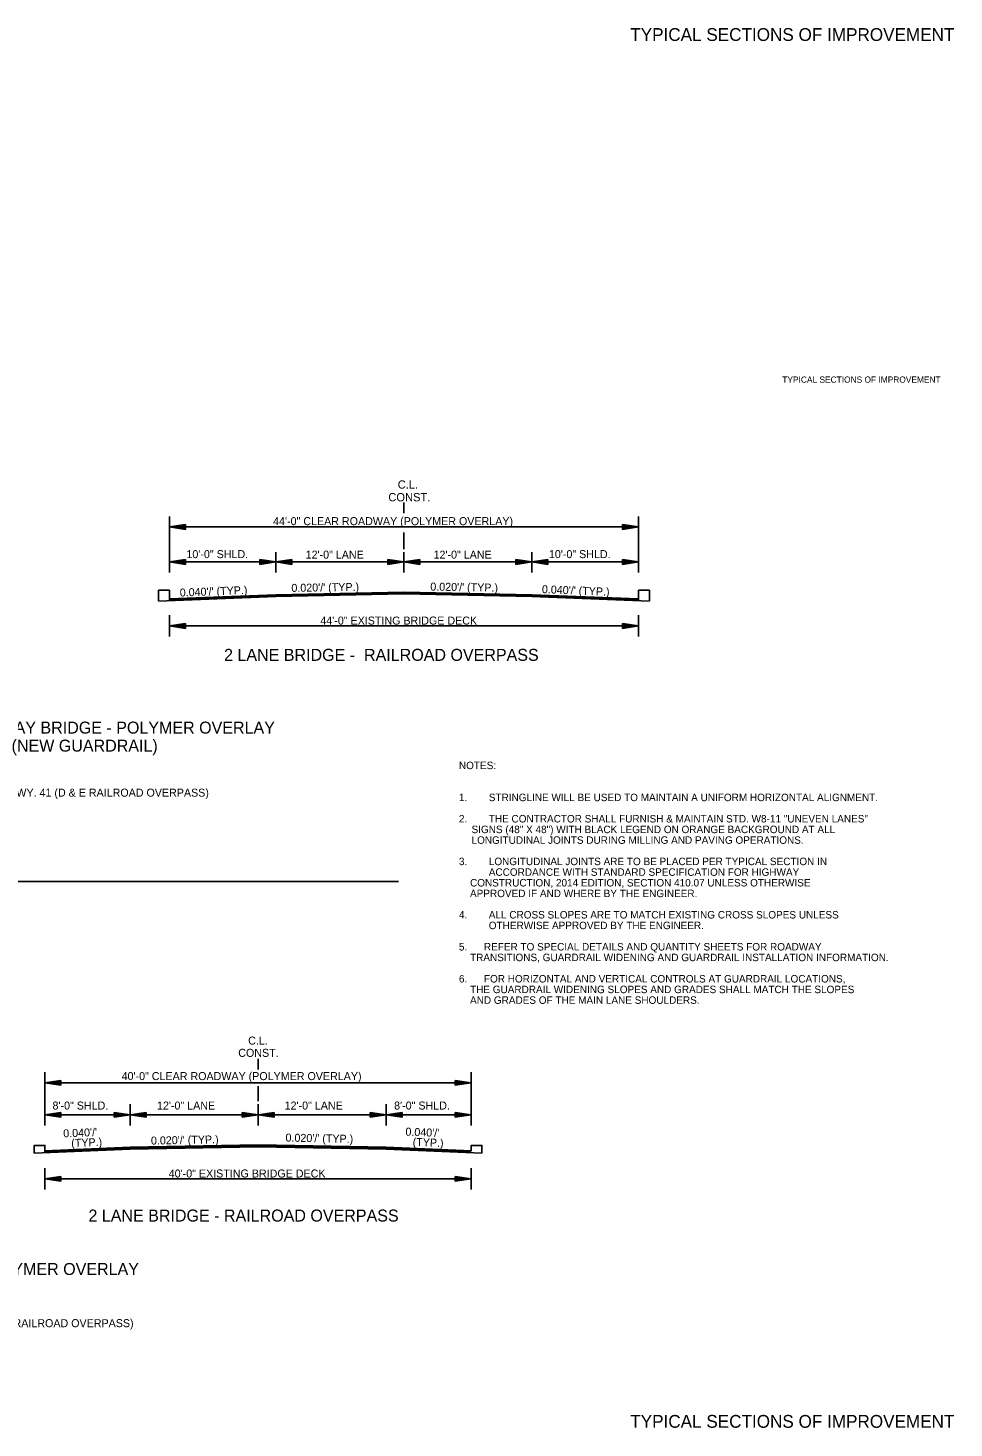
# Model space of a CAD drawing. Extents: x 545241 to 1930787, y -1971772 to 596640.
# Drawn here: x 547399 to 548268, y -1956172 to -1954859 of the extents above; entities that cross this region are included whole.
import ezdxf

# ---------------------------------------------------------------- set-up
doc = ezdxf.new("R2010")
doc.units = 0
for name, color, linetype in [('R_Border', 7, 'Continuous'), ('R_Border Notes', 7, 'Continuous'), ('R_Border Prem', 7, 'Continuous'), ('R_Draft', 7, 'Continuous')]:
    doc.layers.add(name, color=color, linetype=linetype)

# ---------------------------------------------------------------- blocks, each defined once
blk = doc.blocks.new('ARROW')
at = {"layer": 'R_Draft'}
for p, q in [((-2, 0.3), (0, 0)), ((-2, 0.3), (-2, -0.3)), ((-2, 0.25), (-0.334, 0)), ((-2, 0.199), (-0.678, 0)), ((-2, 0.149), (-1.011, 0)), ((-2, 0.097), (-1.35, 0)), ((-2, 0.047), (-1.684, 0)), ((-2, -0.3), (0, 0)), ((-2, -0.098), (-1.35, 0)), ((-2, -0.199), (-0.678, 0)), ((-2, -0.25), (-0.334, 0)), ((-2, -0.149), (-1.011, 0)), ((-2, -0.047), (-1.684, 0))]:
    blk.add_line(p, q, dxfattribs=at)

msp = doc.modelspace()

# ---------------------------------------------------------------- linework, layer by layer
at = {"layer": 'R_Border'}
for p, q in [((547521.7, -1955386.5), (547521.7, -1955396.4)), ((547531.9, -1955386.5), (547521.7, -1955386.5)), ((547531.9, -1955396), (547531.9, -1955386.5)), ((547971.9, -1955396), (547971.9, -1955386.5)), ((547971.9, -1955386.5), (547982.1, -1955386.5)), ((547982.1, -1955386.5), (547982.1, -1955396.4)), ((546718.9, -1955659.5), (547746.9, -1955659.5)), ((547615.1, -1955825.8), (547615.1, -1955835.8)), ((547415.1, -1955838.3), (547415.1, -1955888.3)), ((547815.1, -1955838.3), (547815.1, -1955888.3)), ((547415.1, -1955848.3), (547815.1, -1955848.3)), ((547615.1, -1955851.3), (547615.1, -1955865.3)), ((547495.1, -1955868.3), (547495.1, -1955888.3)), ((547615.1, -1955868.3), (547615.1, -1955888.3)), ((547735.1, -1955868.3), (547735.1, -1955888.3)), ((547415.1, -1955878.3), (547815.1, -1955878.3)), ((547415.1, -1955928.3), (547415.1, -1955948.3)), ((547815.1, -1955928.3), (547815.1, -1955948.3)), ((547415.1, -1955938.3), (547815.1, -1955938.3))]:
    msp.add_line(p, q, dxfattribs=at)
for points in [[(547415.1, -1955913.4), (547415.1, -1955906.9), (547405.1, -1955906.9), (547405.1, -1955914.1)], [(547405.1, -1955914.1), (547495.1, -1955910.5), (547615.1, -1955908.1), (547735.1, -1955910.5), (547825.1, -1955914.1)], [(547415.1, -1955911.9), (547495.1, -1955908.7), (547615.1, -1955906.3), (547735.1, -1955908.7), (547815.1, -1955911.9)], [(547415.1, -1955912.2), (547495.1, -1955909), (547615.1, -1955906.6), (547735.1, -1955909), (547815.1, -1955912.2)], [(547415.1, -1955912.5), (547495.1, -1955909.3), (547615.1, -1955906.9), (547735.1, -1955909.3), (547815.1, -1955912.5)], [(547415.1, -1955912.8), (547495.1, -1955909.6), (547615.1, -1955907.2), (547735.1, -1955909.6), (547815.1, -1955912.8)], [(547415.1, -1955913.1), (547495.1, -1955909.9), (547615.1, -1955907.5), (547735.1, -1955909.9), (547815.1, -1955913.1)], [(547415.1, -1955913.4), (547495.1, -1955910.2), (547615.1, -1955907.8), (547735.1, -1955910.2), (547815.1, -1955913.4)], [(547815.1, -1955911.9), (547815.1, -1955906.9), (547825.1, -1955906.9), (547825.1, -1955914.1)]]:
    msp.add_lwpolyline(points, dxfattribs=at)
at = {"layer": 'R_Draft'}
for p, q in [((547751.9, -1955314.2), (547751.9, -1955304.2)), ((547531.9, -1955370), (547531.9, -1955317.3)), ((547971.9, -1955370), (547971.9, -1955317.3)), ((547546.9, -1955325), (547531.9, -1955327.2)), ((547971.9, -1955327.2), (547531.9, -1955327.2)), ((547546.9, -1955329.5), (547531.9, -1955327.2)), ((547546.9, -1955325.3), (547534.4, -1955327.2)), ((547546.9, -1955329.1), (547534.4, -1955327.2)), ((547546.9, -1955325.7), (547537, -1955327.2)), ((547546.9, -1955328.7), (547537, -1955327.2)), ((547546.9, -1955326.1), (547539.5, -1955327.2)), ((547546.9, -1955328.3), (547539.5, -1955327.2)), ((547546.9, -1955326.5), (547542, -1955327.2)), ((547546.9, -1955327.9), (547542, -1955327.2)), ((547546.9, -1955326.9), (547544.5, -1955327.2)), ((547546.9, -1955327.6), (547544.5, -1955327.2)), ((547546.9, -1955325), (547546.9, -1955329.5)), ((547921.9, -1955327.2), (547641.9, -1955327.2)), ((547956.9, -1955325), (547971.9, -1955327.2)), ((547956.9, -1955329.5), (547956.9, -1955325)), ((547956.9, -1955325.3), (547969.4, -1955327.2)), ((547956.9, -1955325.7), (547966.8, -1955327.2)), ((547956.9, -1955326.1), (547964.3, -1955327.2)), ((547956.9, -1955326.5), (547961.8, -1955327.2)), ((547956.9, -1955326.9), (547959.3, -1955327.2)), ((547956.9, -1955329.5), (547971.9, -1955327.2)), ((547956.9, -1955327.9), (547961.8, -1955327.2)), ((547956.9, -1955328.7), (547966.8, -1955327.2)), ((547956.9, -1955329.1), (547969.4, -1955327.2)), ((547956.9, -1955328.3), (547964.3, -1955327.2)), ((547956.9, -1955327.6), (547959.3, -1955327.2)), ((547751.9, -1955348), (547751.9, -1955332.3)), ((547631.9, -1955370), (547631.9, -1955350.9)), ((547751.9, -1955370), (547751.9, -1955350.9)), ((547871.9, -1955370), (547871.9, -1955350.9)), ((547546.9, -1955357.8), (547531.9, -1955360)), ((547631.9, -1955360), (547531.9, -1955360)), ((547546.9, -1955362.3), (547531.9, -1955360)), ((547546.9, -1955358.2), (547534.4, -1955360)), ((547546.9, -1955361.9), (547534.4, -1955360)), ((547546.9, -1955358.5), (547537, -1955360)), ((547546.9, -1955361.5), (547537, -1955360)), ((547546.9, -1955358.9), (547539.5, -1955360)), ((547546.9, -1955361.2), (547539.5, -1955360)), ((547546.9, -1955359.3), (547542, -1955360)), ((547546.9, -1955360.8), (547542, -1955360)), ((547546.9, -1955359.7), (547544.5, -1955360)), ((547546.9, -1955360.4), (547544.5, -1955360)), ((547546.9, -1955357.8), (547546.9, -1955362.3)), ((547616.9, -1955357.8), (547631.9, -1955360)), ((547616.9, -1955357.8), (547616.9, -1955362.3)), ((547616.9, -1955358.2), (547629.4, -1955360)), ((547616.9, -1955358.5), (547626.8, -1955360)), ((547616.9, -1955358.9), (547624.3, -1955360)), ((547616.9, -1955359.3), (547621.8, -1955360)), ((547616.9, -1955359.7), (547619.3, -1955360)), ((547616.9, -1955362.3), (547631.9, -1955360)), ((547616.9, -1955360.8), (547621.8, -1955360)), ((547616.9, -1955361.5), (547626.8, -1955360)), ((547616.9, -1955361.9), (547629.4, -1955360)), ((547616.9, -1955361.2), (547624.3, -1955360)), ((547616.9, -1955360.4), (547619.3, -1955360)), ((547646.9, -1955357.8), (547631.9, -1955360)), ((547751.9, -1955360), (547631.9, -1955360)), ((547646.9, -1955362.3), (547631.9, -1955360)), ((547646.9, -1955358.2), (547634.4, -1955360)), ((547646.9, -1955361.9), (547634.4, -1955360)), ((547646.9, -1955358.5), (547637, -1955360)), ((547646.9, -1955361.5), (547637, -1955360)), ((547646.9, -1955358.9), (547639.5, -1955360)), ((547646.9, -1955361.2), (547639.5, -1955360)), ((547646.9, -1955359.3), (547642, -1955360)), ((547646.9, -1955360.8), (547642, -1955360)), ((547646.9, -1955359.7), (547644.5, -1955360)), ((547646.9, -1955360.4), (547644.5, -1955360)), ((547646.9, -1955357.8), (547646.9, -1955362.3)), ((547736.9, -1955357.8), (547751.9, -1955360)), ((547736.9, -1955357.8), (547736.9, -1955362.3)), ((547736.9, -1955358.2), (547749.4, -1955360)), ((547736.9, -1955358.5), (547746.8, -1955360)), ((547736.9, -1955358.9), (547744.3, -1955360)), ((547736.9, -1955359.3), (547741.8, -1955360)), ((547736.9, -1955359.7), (547739.3, -1955360)), ((547736.9, -1955362.3), (547751.9, -1955360)), ((547736.9, -1955360.8), (547741.8, -1955360)), ((547736.9, -1955361.5), (547746.8, -1955360)), ((547736.9, -1955361.9), (547749.4, -1955360)), ((547736.9, -1955361.2), (547744.3, -1955360)), ((547736.9, -1955360.4), (547739.3, -1955360)), ((547766.9, -1955357.8), (547751.9, -1955360)), ((547871.9, -1955360), (547751.9, -1955360)), ((547766.9, -1955362.3), (547751.9, -1955360)), ((547766.9, -1955358.2), (547754.4, -1955360)), ((547766.9, -1955361.9), (547754.4, -1955360)), ((547766.9, -1955358.5), (547757, -1955360)), ((547766.9, -1955361.5), (547757, -1955360)), ((547766.9, -1955358.9), (547759.5, -1955360)), ((547766.9, -1955361.2), (547759.5, -1955360)), ((547766.9, -1955359.3), (547762, -1955360)), ((547766.9, -1955360.8), (547762, -1955360)), ((547766.9, -1955359.7), (547764.5, -1955360)), ((547766.9, -1955360.4), (547764.5, -1955360)), ((547766.9, -1955357.8), (547766.9, -1955362.3)), ((547856.9, -1955357.8), (547871.9, -1955360)), ((547856.9, -1955357.8), (547856.9, -1955362.3)), ((547856.9, -1955358.2), (547869.4, -1955360)), ((547856.9, -1955358.5), (547866.8, -1955360)), ((547856.9, -1955358.9), (547864.3, -1955360)), ((547856.9, -1955359.3), (547861.8, -1955360)), ((547856.9, -1955359.7), (547859.3, -1955360)), ((547856.9, -1955362.3), (547871.9, -1955360)), ((547856.9, -1955360.8), (547861.8, -1955360)), ((547856.9, -1955361.5), (547866.8, -1955360)), ((547856.9, -1955361.9), (547869.4, -1955360)), ((547856.9, -1955361.2), (547864.3, -1955360)), ((547856.9, -1955360.4), (547859.3, -1955360)), ((547886.9, -1955357.8), (547871.9, -1955360)), ((547871.9, -1955360), (547971.9, -1955360)), ((547886.9, -1955362.3), (547871.9, -1955360)), ((547886.9, -1955358.2), (547874.4, -1955360)), ((547886.9, -1955361.9), (547874.4, -1955360)), ((547886.9, -1955358.5), (547877, -1955360)), ((547886.9, -1955361.5), (547877, -1955360)), ((547886.9, -1955358.9), (547879.5, -1955360)), ((547886.9, -1955361.2), (547879.5, -1955360)), ((547886.9, -1955359.3), (547882, -1955360)), ((547886.9, -1955360.8), (547882, -1955360)), ((547886.9, -1955359.7), (547884.5, -1955360)), ((547886.9, -1955360.4), (547884.5, -1955360)), ((547886.9, -1955357.8), (547886.9, -1955362.3)), ((547956.9, -1955357.8), (547971.9, -1955360)), ((547956.9, -1955357.8), (547956.9, -1955362.3)), ((547956.9, -1955358.2), (547969.4, -1955360)), ((547956.9, -1955358.5), (547966.8, -1955360)), ((547956.9, -1955358.9), (547964.3, -1955360)), ((547956.9, -1955359.3), (547961.8, -1955360)), ((547956.9, -1955359.7), (547959.3, -1955360)), ((547956.9, -1955362.3), (547971.9, -1955360)), ((547956.9, -1955360.8), (547961.8, -1955360)), ((547956.9, -1955361.5), (547966.8, -1955360)), ((547956.9, -1955361.9), (547969.4, -1955360)), ((547956.9, -1955361.2), (547964.3, -1955360)), ((547956.9, -1955360.4), (547959.3, -1955360)), ((547631.9, -1955392.3), (547521.7, -1955396.7)), ((547631.9, -1955390.7), (547531.9, -1955394.7)), ((547631.9, -1955391), (547531.9, -1955395)), ((547631.9, -1955391.3), (547531.9, -1955395.3)), ((547631.9, -1955391.6), (547531.9, -1955395.6)), ((547631.9, -1955392), (547531.9, -1955396)), ((547751.9, -1955388.3), (547631.9, -1955390.7)), ((547751.9, -1955388.6), (547631.9, -1955391)), ((547751.9, -1955388.9), (547631.9, -1955391.3)), ((547751.9, -1955389.2), (547631.9, -1955391.6)), ((547751.9, -1955389.5), (547631.9, -1955392)), ((547751.9, -1955389.8), (547631.9, -1955392.3)), ((547751.9, -1955390), (547631.9, -1955392.4)), ((547751.9, -1955388.3), (547871.9, -1955390.7)), ((547751.9, -1955388.6), (547871.9, -1955391)), ((547751.9, -1955388.9), (547871.9, -1955391.3)), ((547751.9, -1955389.2), (547871.9, -1955391.6)), ((547751.9, -1955389.5), (547871.9, -1955392)), ((547751.9, -1955389.8), (547871.9, -1955392.3)), ((547751.9, -1955390), (547871.9, -1955392.4)), ((547871.9, -1955390.7), (547971.9, -1955394.7)), ((547871.9, -1955391), (547971.9, -1955395)), ((547871.9, -1955391.3), (547971.9, -1955395.3)), ((547871.9, -1955391.6), (547971.9, -1955395.6)), ((547871.9, -1955392), (547971.9, -1955396)), ((547871.9, -1955392.3), (547982.1, -1955396.7)), ((547531.9, -1955410), (547531.9, -1955430)), ((547971.9, -1955409.8), (547971.9, -1955429.8)), ((547546.9, -1955417.8), (547531.9, -1955420)), ((547546.9, -1955422.3), (547531.9, -1955420)), ((547971.9, -1955420), (547531.9, -1955420)), ((547546.9, -1955418.1), (547534.4, -1955420)), ((547546.9, -1955421.9), (547534.4, -1955420)), ((547546.9, -1955418.5), (547537, -1955420)), ((547546.9, -1955421.5), (547537, -1955420)), ((547546.9, -1955418.9), (547539.5, -1955420)), ((547546.9, -1955421.1), (547539.5, -1955420)), ((547546.9, -1955419.3), (547542, -1955420)), ((547546.9, -1955420.7), (547542, -1955420)), ((547546.9, -1955419.7), (547544.5, -1955420)), ((547546.9, -1955420.4), (547544.5, -1955420)), ((547546.9, -1955417.8), (547546.9, -1955422.3)), ((547956.9, -1955417.8), (547971.9, -1955420)), ((547956.9, -1955422.3), (547956.9, -1955417.8)), ((547956.9, -1955418.1), (547969.4, -1955420)), ((547956.9, -1955418.5), (547966.8, -1955420)), ((547956.9, -1955418.9), (547964.3, -1955420)), ((547956.9, -1955419.3), (547961.8, -1955420)), ((547956.9, -1955419.7), (547959.3, -1955420)), ((547956.9, -1955422.3), (547971.9, -1955420)), ((547956.9, -1955420.7), (547961.8, -1955420)), ((547956.9, -1955421.5), (547966.8, -1955420)), ((547956.9, -1955421.9), (547969.4, -1955420)), ((547956.9, -1955421.1), (547964.3, -1955420)), ((547956.9, -1955420.4), (547959.3, -1955420))]:
    msp.add_line(p, q, dxfattribs=at)

# ---------------------------------------------------------------- block references
at = {"layer": 'R_Border', "xscale": 7.5, "yscale": 7.5, "rotation": 180}
for p in [(547415.1, -1955848.3), (547415.1, -1955878.3), (547495.1, -1955878.3), (547615.1, -1955878.3), (547735.1, -1955878.3), (547415.1, -1955938.3)]:
    msp.add_blockref('ARROW', p, dxfattribs=at)
at = {"layer": 'R_Border', "xscale": 7.5, "yscale": 7.5}
for p in [(547815.1, -1955848.3), (547495.1, -1955878.3), (547615.1, -1955878.3), (547735.1, -1955878.3), (547815.1, -1955878.3), (547815.1, -1955938.3)]:
    msp.add_blockref('ARROW', p, dxfattribs=at)

# ---------------------------------------------------------------- texts
at = {"layer": 'R_Border'}
for s, height, rotation, p in [('TYPICAL SECTIONS OF IMPROVEMENT', 12, 360, (547964.2, -1954871.6)), ("0.040'/'", 7.5, 2.2916, (547432.5, -1955899.4)), ("0.040'/'", 7.5, 357.7084, (547753.2, -1955897.7)), ('(TYP.)', 7.5, 2.2916, (547440, -1955908.5)), ("0.020'/' (TYP.)", 7.5, 1.1458, (547514.7, -1955906.2)), ("0.020'/' (TYP.)", 7.5, 358.8542, (547640.8, -1955903.3)), ('(TYP.)', 7.5, 357.7084, (547760, -1955907.3)), ('TYPICAL SECTIONS OF IMPROVEMENT', 12, 360, (547964.2, -1956171.6))]:
    msp.add_text(s, height=height, rotation=rotation, dxfattribs=at).set_placement(p)
for s, height, p in [('CONST.', 7.5, (547596.5, -1955823.9)), ('C.L.', 7.5, (547605.8, -1955812.4)), ('40\'-0" CLEAR ROADWAY (POLYMER OVERLAY)', 7.5, (547487.1, -1955845.7)), ('8\'-0" SHLD.', 7.5, (547422.3, -1955873.3)), ('12\'-0" LANE', 7.5, (547520.3, -1955873.3)), ('12\'-0" LANE', 7.5, (547640, -1955873.3)), ('8\'-0" SHLD.', 7.5, (547742.7, -1955873.3)), ('40\'-0" EXISTING BRIDGE DECK', 7.5, (547531.3, -1955937)), ('2 LANE BRIDGE - RAILROAD OVERPASS', 11.25, (547456, -1955978.3)), ('40 FT. CLEAR ROADWAY BRIDGE - POLYMER OVERLAY', 11.25, (547099.6, -1956028.4))]:
    msp.add_text(s, height=height, dxfattribs=at).set_placement(p)
at = {"layer": 'R_Border Notes'}
for s, p in [('NOTES: ', (547803.5, -1955554.2)), ('1.', (547803.5, -1955584.2)), ('STRINGLINE WILL BE USED TO MAINTAIN A UNIFORM HORIZONTAL ALIGNMENT.', (547831.5, -1955584.2)), ('2.', (547803.5, -1955604.2)), ('    SIGNS (48" X 48") WITH BLACK LEGEND ON ORANGE BACKGROUND AT ALL ', (547804.9, -1955614.2)), ('THE CONTRACTOR SHALL FURNISH & MAINTAIN STD. W8-11 "UNEVEN LANES" ', (547831.5, -1955604.2)), ('    LONGITUDINAL JOINTS DURING MILLING AND PAVING OPERATIONS.', (547804.9, -1955624.2)), ('3.', (547803.5, -1955644.2)), ('LONGITUDINAL JOINTS ARE TO BE PLACED PER TYPICAL SECTION IN ', (547831.5, -1955644.2)), ('    CONSTRUCTION, 2014 EDITION, SECTION 410.07 UNLESS OTHERWISE', (547803.5, -1955664.2)), ('ACCORDANCE WITH STANDARD SPECIFICATION FOR HIGHWAY', (547831.5, -1955654.2)), ('    APPROVED IF AND WHERE BY THE ENGINEER.', (547803.5, -1955674.2)), ('4.', (547803.5, -1955694.2)), ('ALL CROSS SLOPES ARE TO MATCH EXISTING CROSS SLOPES UNLESS ', (547831.5, -1955694.2)), ('OTHERWISE APPROVED BY THE ENGINEER.', (547831.5, -1955704.2)), ('5.      REFER TO SPECIAL DETAILS AND QUANTITY SHEETS FOR ROADWAY', (547803.5, -1955724.2)), ('    TRANSITIONS, GUARDRAIL WIDENING AND GUARDRAIL INSTALLATION INFORMATION.', (547803.5, -1955734.2)), ('6.      FOR HORIZONTAL AND VERTICAL CONTROLS AT GUARDRAIL LOCATIONS,', (547803.5, -1955754.2)), ('    THE GUARDRAIL WIDENING SLOPES AND GRADES SHALL MATCH THE SLOPES', (547803.5, -1955764.2)), ('    AND GRADES OF THE MAIN LANE SHOULDERS.  ', (547803.5, -1955774.2))]:
    msp.add_text(s, height=7, dxfattribs=at).set_placement(p)
at = {"layer": 'R_Border Prem'}
msp.add_text('TYPICAL SECTIONS OF IMPROVEMENT', height=5.862, rotation=360, dxfattribs=at).set_placement((548106.8, -1955192))
at = {"layer": 'R_Draft'}
for s, height, p in [('C.L.', 7.8, (547746.1, -1955291.3)), ('CONST.', 7.8, (547737.3, -1955303.2)), ('44\'-0" CLEAR ROADWAY (POLYMER OVERLAY)', 7.5, (547629.2, -1955325.5)), ('10\'-0" SHLD.', 7.5, (547547.9, -1955356.4)), ('12\'-0" LANE', 7.5, (547659.7, -1955356.9)), ('12\'-0" LANE', 7.5, (547779.7, -1955356.9)), ('10\'-0" SHLD.', 7.5, (547887.9, -1955356.4)), ('44\'-0" EXISTING BRIDGE DECK', 7.5, (547673.5, -1955418.7)), ('2 LANE BRIDGE -  RAILROAD OVERPASS ', 11.25, (547583.2, -1955452.7)), ('44 FT. CLEAR ROADWAY BRIDGE - POLYMER OVERLAY', 11.25, (547227.1, -1955520.9)), ('(NEW GUARDRAIL)', 11.25, (547383.9, -1955537.8)), ('- BR. NO. 05685 - HWY. 41 (D & E RAILROAD OVERPASS)', 7.5, (547298.1, -1955580)), ('(KANSAS CITY RAILROAD OVERPASS)', 7.5, (547313.3, -1956077.3))]:
    msp.add_text(s, height=height, dxfattribs=at).set_placement(p)
for s, rotation, p in [("0.040'/' (TYP.)", 2.2906, (547541.8, -1955392.5)), ("0.020'/' (TYP.)", 0.9719, (547646.4, -1955388.1)), ("0.020'/' (TYP.)", 359.0281, (547776.6, -1955386.8)), ("0.040'/' (TYP.)", 357.7094, (547881.2, -1955389.2))]:
    msp.add_text(s, height=7.5, rotation=rotation, dxfattribs=at).set_placement(p)

doc.saveas('drawing.dxf')
